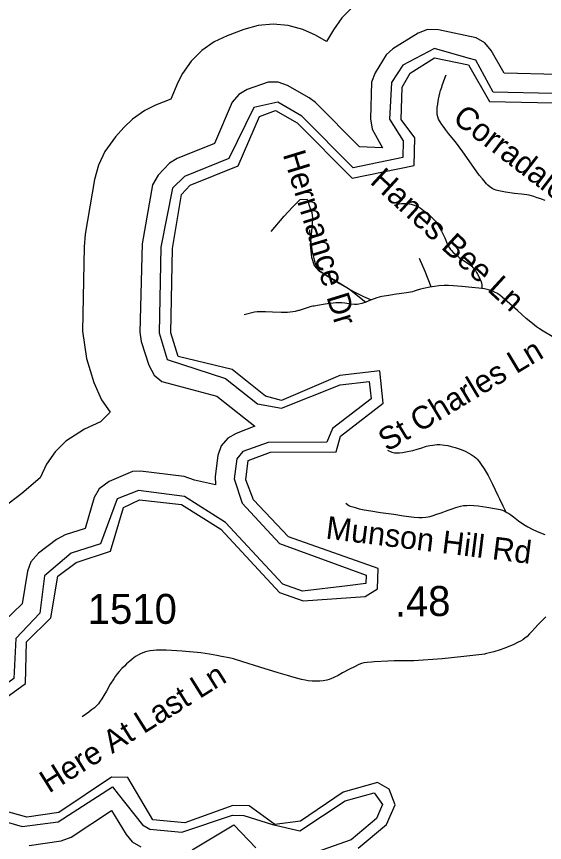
# Model space of a CAD drawing. Extents: x 1383679 to 1536984, y 460658 to 651027.
# Drawn here: x 1385529 to 1387731, y 489995 to 493439 of the extents above; entities that cross this region are included whole.
import ezdxf

# ---------------------------------------------------------------- set-up
doc = ezdxf.new("R2010")
doc.units = 0
for name, color, linetype in [('Exist Hydrographic Bay Label', 7, 'Continuous'), ('Exist Hydrographic Buffer Line', 7, 'Continuous'), ('Exist Road Non-System Type 51', 7, 'Continuous'), ('Exist Road Non-System Type 51 Label', 7, 'Continuous'), ('Exist Road Secondary Mileage Hundredths English Label', 7, 'Continuous'), ('Exist Road Secondary Type 41 Attributed', 7, 'Continuous'), ('Exist Road Secondary Type 51 Label', 7, 'Continuous'), ('Exist Road Secondary Type 51 Number Label', 7, 'Continuous')]:
    doc.layers.add(name, color=color, linetype=linetype)

msp = doc.modelspace()

# ---------------------------------------------------------------- linework, layer by layer
at = {"layer": 'Exist Hydrographic Bay Label'}
for points in [[(1385974.5, 491392), (1386041.5, 491423.5), (1386216.5, 491403.6), (1386380.4, 491301.8), (1386625.4, 491037.5), (1386724.5, 491002.7), (1386983.4, 491020.5), (1387034.4, 491052.3), (1387036.4, 491137.7), (1386663.5, 491269.9), (1386516.4, 491423.8), (1386485.5, 491506.5), (1386495.4, 491588.3), (1386587.4, 491622.6), (1386862.5, 491623.6), (1386880.4, 491688.9), (1387058.4, 491826.4), (1387044.4, 491961.3), (1386877.4, 491941.7), (1386633.4, 491838.3), (1386567.4, 491856), (1386427.5, 491967.1), (1386203.4, 492020.9), (1386172.5, 492120), (1386179.5, 492471.1), (1386217.5, 492696.8), (1386252.5, 492735.5), (1386453.4, 492816.8), (1386541.5, 493021.8), (1386608.4, 493046.7), (1386699.5, 492995.7), (1386928.4, 492764.6), (1387187.4, 492818.5), (1387190.4, 492933.3), (1387133.4, 493010), (1387136.4, 493144.5), (1387170.4, 493202.9), (1387272.4, 493266.5), (1387413.4, 493237.4), (1387501.4, 493084.6), (1387768.4, 493079.3)], [(1385355.5, 490505), (1385566.5, 490658.3), (1385570.5, 490832.2), (1385672.5, 490931.9), (1385701.5, 491105.3), (1385777.5, 491162.9), (1385920.5, 491209.2), (1385974.5, 491392)], [(1386953.4, 489970.8), (1387072.4, 490070.1), (1387107.4, 490151.5), (1387083.4, 490217.6), (1387034.4, 490244.8), (1386891.4, 490205.1), (1386713.4, 490083.8), (1386605.4, 490069.6), (1386498.4, 490147.3), (1386431.4, 490148.6), (1386230.4, 490077.2), (1386097.4, 490089.6), (1385992.5, 490265.7), (1385925.5, 490267.1), (1385705.5, 490120.5), (1385572.5, 490100.2), (1385381.5, 490153.3)]]:
    msp.add_lwpolyline(points, dxfattribs=at)
at = {"layer": 'Exist Hydrographic Buffer Line'}
for p, q in [((1386619.2, 493081.6), (1386518.7, 493059.3)), ((1386533.7, 491824.7), (1386633.6, 491806.3))]:
    msp.add_line(p, q, dxfattribs=at)
for points in [[(1386930.3, 493478.6), (1386885.9, 493434.2), (1386850.7, 493384.1), (1386821.9, 493334.8), (1386775.7, 493360.7), (1386722.7, 493385), (1386662.2, 493401.2), (1386599.6, 493406.7), (1386537.1, 493401.2), (1386476.5, 493385), (1386407.1, 493359.2), (1386352.6, 493333.6), (1386301.3, 493297.6), (1386256.9, 493253.2), (1386220.9, 493201.8), (1386201.9, 493163.8), (1386172.3, 493094.9), (1386108.7, 493069.3), (1386063.6, 493047.3), (1386012.2, 493011.3), (1385976.4, 492976.6), (1385941.4, 492937.9), (1385896.9, 492876.7), (1385870.3, 492819.9), (1385854.1, 492759.2), (1385815.7, 492530.9), (1385810.7, 492478.2), (1385803.7, 492127.1), (1385820.1, 492012.6), (1385851.1, 491913.5), (1385882.8, 491840.9), (1385918.8, 491789.5), (1385879.5, 491749.2), (1385812.5, 491717.8), (1385734.3, 491667.8), (1385689.9, 491623.4), (1385653.9, 491572), (1385627.4, 491515.1), (1385551.2, 491449.8), (1385475.2, 491392.2)], [(1387783.5, 493196.8), (1387562.7, 493203.2), (1387508.6, 493297.2), (1387481.7, 493329.2), (1387445.7, 493350.1), (1387287.9, 493384), (1387242.8, 493384.6), (1387203.6, 493370.3), (1387098.1, 493304.6), (1387069.7, 493280), (1387024, 493204.9), (1387009.4, 493165.2), (1387004.7, 493012.6), (1387011.9, 492968.8), (1387054.8, 492891.1), (1386959, 492895.3), (1386775.9, 493080.1)], [(1387412.6, 493264.9), (1387271.7, 493305.6), (1387140.4, 493236.7), (1387093.1, 493164.6), (1387084.7, 493010.8), (1387141.3, 492920.4), (1387139.4, 492851.1), (1386932.7, 492808.1), (1386719.1, 493023.8), (1386619.2, 493081.6)], [(1389588.2, 491540.1), (1389338.3, 491817.7), (1389047.3, 491821.9), (1389043.8, 491936.8), (1389066.1, 491987), (1389072.5, 492143.6), (1389002.9, 492227.1), (1388866.4, 492265.3), (1388869.5, 492400.2), (1388843.5, 492486.5), (1388767.8, 492563.6), (1388464.1, 492683.2), (1388410.9, 492732.7), (1388318.2, 492943.6), (1388233, 493019), (1387767.6, 493118.4), (1387516, 493124.1), (1387444.3, 493257), (1387412.6, 493264.9)], [(1386775.9, 493080.1), (1386749.4, 493100.3), (1386658.4, 493151.4), (1386620.4, 493164.9), (1386578.8, 493164.9), (1386490.8, 493134.3), (1386455.6, 493113.7), (1386428.7, 493081.8), (1386353.9, 492909.5), (1386198.6, 492846.7), (1386166.5, 492827.4), (1386119.6, 492777.1), (1386095.9, 492737.8), (1386052.3, 492491), (1386043.7, 492122.3), (1386049.1, 492084.2), (1386080.1, 491985.1), (1386102.7, 491943.7), (1386134.7, 491917), (1386364.8, 491856.6), (1386484, 491762.1), (1386522.3, 491731.3)], [(1386619.2, 493081.6), (1386518.7, 493059.3), (1386414.3, 492847.7), (1386228.7, 492772.6), (1386178.9, 492723.5), (1386131.2, 492477.7), (1386123.7, 492120.7), (1386156.5, 492008.9), (1386400.7, 491930.3), (1386533.7, 491824.7)], [(1386633.6, 491806.3), (1386879, 491902.6), (1387000.1, 491916.8), (1387007.6, 491844.4), (1386847.1, 491720.6), (1386823.1, 491663.5), (1386578.5, 491662.6), (1386472.7, 491625.8), (1386447.3, 491595.2), (1386437, 491511.3), (1386470.2, 491409.7), (1386625.8, 491242.2), (1386987, 491109.6), (1386986.1, 491074.8), (1386909.3, 491065.6), (1386721.1, 491043.1), (1386639.2, 491072), (1386400.9, 491329), (1386228.8, 491437.6), (1386037.2, 491463.2), (1385948.7, 491428.2), (1385879.3, 491240.8), (1385756.3, 491200.9)], [(1386522.3, 491731.3), (1386444.8, 491700.8), (1386409.5, 491680.2), (1386382.7, 491648.3), (1386368.4, 491609.1), (1386357.5, 491520.9), (1386358.5, 491485.6)], [(1386358.5, 491485.6), (1386270.9, 491505.5), (1386228.5, 491521.7), (1386046.2, 491542.7), (1386011.8, 491541.6), (1385914.6, 491500.6), (1385873.7, 491469.1), (1385852.9, 491433.1), (1385814.5, 491303.9), (1385731.6, 491277.1), (1385696.2, 491258.6), (1385620.2, 491201), (1385588.7, 491165.3), (1385574.5, 491126.1), (1385551.8, 490990.4), (1385477.8, 490918)], [(1385756.3, 491200.9), (1385645.1, 491107.4), (1385626.3, 490951.4), (1385526.4, 490845), (1385518.1, 490679), (1385323.2, 490537.4), (1385246.9, 490335.3)], [(1385246.9, 490335.3), (1385271.4, 490178.9), (1385350.5, 490120.1), (1385552.9, 490061.7), (1385702.7, 490081), (1385928.4, 490226.9), (1385952.5, 490196.7), (1386054.3, 490069.1), (1386084.9, 490049.8), (1386217.9, 490037.4), (1386429.1, 490108.5), (1386476.3, 490107.5), (1386596.6, 490069.6), (1386709.8, 490044.1), (1386899.6, 490168.3), (1387020.5, 490201.9), (1387055.6, 490152.7), (1387030.6, 490094.6), (1386924.5, 490006), (1386755.2, 489946.3)], [(1385581.8, 489981.6), (1385714.8, 490001.9), (1385756.6, 490016.6), (1385925.5, 490128.8), (1385985.6, 490028.2), (1386011.5, 489997.7), (1386047.6, 489976.9)], [(1386261.8, 489964.1), (1386435.7, 490068.3), (1386526.2, 489972.5)]]:
    msp.add_lwpolyline(points, dxfattribs=at)
at = {"layer": 'Exist Road Non-System Type 51'}
for points in [[(1387732.8, 492672.3), (1387717.8, 492677.3), (1387714.7, 492678.4), (1387700.1, 492683.2), (1387685.5, 492688.1), (1387667.1, 492693.7), (1387656.7, 492695.7), (1387635.2, 492698.5), (1387605.6, 492701.6), (1387567.4, 492706.7), (1387553.9, 492708.9), (1387540, 492711.7), (1387529.6, 492714.5), (1387521.2, 492717.6), (1387512.3, 492722.1), (1387502.1, 492729.2), (1387494.6, 492736), (1387489.4, 492741.4), (1387471.6, 492762.3), (1387458.5, 492778), (1387426, 492824), (1387389.8, 492874.7), (1387359.5, 492916.3), (1387330.5, 492951.8), (1387318.3, 492968.1), (1387311.6, 492976.5), (1387302, 492989.4), (1387294.9, 493000.5), (1387293.1, 493004.2), (1387289.1, 493011.8), (1387285.6, 493020.7), (1387283.6, 493030.1), (1387282.7, 493041.3), (1387282.7, 493054.6), (1387283.7, 493063.1), (1387284.4, 493066), (1387289.1, 493094.8), (1387294.6, 493119.2), (1387297.4, 493130.2), (1387302, 493143.9), (1387304.3, 493151.8), (1387309.5, 493167.2), (1387314.4, 493181.5), (1387320, 493196.6)], [(1386590.2, 492542.8), (1386645.2, 492606.8), (1386680.1, 492643.5), (1386711.2, 492676.5), (1386741, 492677.6), (1386752.1, 492643.2), (1386760.4, 492622.3), (1386763.5, 492598.8), (1386762.4, 492573.2), (1386753.2, 492487.4), (1386759.4, 492435.2), (1386770.6, 492401.5), (1386791, 492377), (1386852.4, 492342.2), (1386916.8, 492302.3), (1386985.8, 492248.3)], [(1387104, 492651.9), (1387116.6, 492655.9), (1387124.7, 492657.8), (1387134.5, 492659), (1387144.6, 492659.4), (1387154.4, 492658.9), (1387165.9, 492657.9), (1387174.2, 492656.5), (1387183.3, 492654.3), (1387194.3, 492650.4), (1387202.3, 492646.6), (1387212, 492640.9), (1387226.3, 492630.6), (1387235.9, 492622.9), (1387242.3, 492617.3), (1387253.3, 492608), (1387260.4, 492601.7), (1387268.8, 492593.3), (1387275.9, 492585.5), (1387280.3, 492579.6), (1387291.9, 492561.3), (1387301.4, 492544.2), (1387314.3, 492516.7), (1387325.4, 492490.7), (1387330.5, 492480.6), (1387333.6, 492475.3), (1387338.5, 492468.2), (1387342.3, 492463.2), (1387349.2, 492455.8), (1387360.3, 492446.1), (1387374.7, 492434.9), (1387401.2, 492416.6), (1387420.2, 492403.1), (1387426.9, 492397.8), (1387432.4, 492392.6), (1387438.4, 492385.6), (1387443.2, 492379.4), (1387447.4, 492372.1), (1387450.9, 492365.2), (1387456.2, 492355.6), (1387461.5, 492344.8), (1387463.7, 492339.6), (1387466.1, 492333.2), (1387467.6, 492328.3), (1387469, 492318.3), (1387469, 492305.4)], [(1386750.7, 492549.6), (1386751.3, 492544.3), (1386757.7, 492487.5), (1386760.7, 492467.2), (1386761.9, 492459.9), (1386763.8, 492451.8), (1386765.3, 492444), (1386767, 492435.7), (1386769.9, 492424.6), (1386772.7, 492415), (1386774.9, 492408.1), (1386777.2, 492401.7), (1386779.7, 492396), (1386783.2, 492390), (1386786, 492386.2), (1386788.9, 492383), (1386794.3, 492378.2), (1386801.8, 492372.7), (1386807.6, 492368.8), (1386812.6, 492365.1), (1386821.2, 492359.8), (1386876.1, 492325.2), (1386934.4, 492292), (1386975.9, 492271.4), (1386985.2, 492267.4), (1387008.1, 492257.6)], [(1387207.8, 492431), (1387231.5, 492377.8), (1387256, 492312.9)], [(1387469, 492305.4), (1387456.8, 492306.4), (1387428.2, 492309.2), (1387386, 492313.8), (1387349.5, 492316.7), (1387330.2, 492317.5), (1387311.7, 492317.4), (1387290.1, 492315.9), (1387271.8, 492314), (1387251.8, 492310.9), (1387225.7, 492305.4), (1387213, 492301.8), (1387199.2, 492297.5), (1387187.7, 492293.7), (1387179.6, 492291.7), (1387154.7, 492286.8), (1387134.1, 492283.6), (1387104, 492279.3), (1387081.3, 492276.1), (1387052.7, 492271.6), (1387041.7, 492268.8), (1387031.3, 492265.8), (1387019.8, 492262.4), (1387008.1, 492257.6)], [(1387845.4, 492055.2), (1387762.4, 492104.5), (1387724.7, 492127.1), (1387710, 492136.9), (1387697.9, 492145), (1387680, 492159.2), (1387654.6, 492179.7), (1387618.7, 492213.5), (1387574.4, 492250.9), (1387554.7, 492268.2), (1387554, 492268.8), (1387544, 492277.1), (1387536.6, 492282.1), (1387532.1, 492284.9), (1387524.4, 492288.7), (1387517.2, 492291.8), (1387509.2, 492295), (1387501.6, 492297.7), (1387496.7, 492299.5), (1387486.6, 492301.9), (1387480.1, 492303.6), (1387469, 492305.4)], [(1387008.1, 492257.6), (1386994.9, 492252.2), (1386986.1, 492248.5), (1386981.8, 492246.7), (1386969.5, 492242.3), (1386956.1, 492239.3), (1386949, 492238.4), (1386938.7, 492238.4), (1386923.2, 492239.9), (1386898.2, 492243.4), (1386885.8, 492244.7), (1386869.7, 492245.7), (1386860.7, 492245.7), (1386848.7, 492244.1), (1386835.7, 492242.1), (1386816.6, 492239.5), (1386784.6, 492234.4), (1386769.7, 492232), (1386764, 492230.9), (1386757.9, 492229.3), (1386707.6, 492213.8), (1386704.7, 492213.1), (1386690.6, 492209.5), (1386680.9, 492207.3), (1386659.4, 492204.9), (1386632.1, 492204.5), (1386596.9, 492206.1), (1386566.5, 492207.2), (1386539.9, 492207.9), (1386532.9, 492207.2), (1386521.5, 492206.4), (1386478.8, 492195.5)], [(1387075.4, 491630.6), (1387093.5, 491622.8), (1387104.9, 491620.1), (1387114, 491619.5), (1387126, 491620.1), (1387139.1, 491621.6), (1387165.7, 491626.3), (1387181.1, 491629.9), (1387199.8, 491635.1), (1387214.8, 491639.6), (1387238.4, 491646.9), (1387252.1, 491650), (1387264.7, 491652.1), (1387281.7, 491653.8), (1387294.6, 491653.8), (1387314.7, 491652.1), (1387327.2, 491650), (1387341.8, 491646.6), (1387357.5, 491642.1), (1387370.7, 491637.9), (1387382.6, 491633.7), (1387399.2, 491626.8), (1387415.1, 491618.8), (1387424.6, 491612.9), (1387437.1, 491604.2), (1387443.6, 491598.6), (1387449.2, 491593.1), (1387457.8, 491583.6), (1387466.5, 491571.5), (1387478.9, 491552.8), (1387495.2, 491524.7), (1387513.8, 491488.7), (1387536.4, 491441.1), (1387542.8, 491428.3), (1387557.3, 491398.9), (1387569.4, 491373.8)], [(1386901.6, 491409.6), (1386914.9, 491400.6), (1386920.5, 491397.8), (1386931.2, 491394), (1386940.5, 491391.5), (1386958.4, 491386.7), (1386978.9, 491382.6), (1387006.5, 491377.3), (1387047.4, 491371), (1387102.4, 491363.4), (1387143.3, 491357.4), (1387187, 491352), (1387206.7, 491350.3), (1387220.3, 491349.9), (1387235.6, 491350.8), (1387246, 491353), (1387253.3, 491354.8), (1387266.8, 491359), (1387277.3, 491362.1), (1387299.1, 491369.7), (1387329.1, 491380.7), (1387345.1, 491386.6), (1387361, 491391.8), (1387380.1, 491396.9), (1387393.4, 491399.4), (1387407.1, 491400.3), (1387418.7, 491400.8), (1387436.6, 491400.5), (1387454.3, 491398.8), (1387489.9, 491393.6), (1387531.1, 491386), (1387538.9, 491384.5), (1387545.4, 491383.2), (1387554.9, 491380.7), (1387561.8, 491378), (1387569.4, 491373.8)], [(1387569.4, 491373.8), (1387573.9, 491371.4), (1387581.3, 491366.8), (1387590.1, 491360.8), (1387601.7, 491352.3), (1387622.3, 491336.8), (1387644.5, 491321), (1387661.5, 491311), (1387679.5, 491300.8), (1387700.4, 491291.2), (1387732, 491278.7)]]:
    msp.add_lwpolyline(points, dxfattribs=at)
at = {"layer": 'Exist Road Secondary Type 41 Attributed'}
for points in [[(1387735.5, 490935.8), (1387725.1, 490925.4), (1387704.6, 490903.8), (1387690.3, 490889.2), (1387677.7, 490875.3), (1387668.1, 490864.9), (1387657.7, 490854.2), (1387649, 490846.2), (1387640.7, 490840.3), (1387631, 490834.7), (1387621.2, 490829.5), (1387602.8, 490820.8), (1387578.8, 490810.4), (1387560.5, 490803.5), (1387545.1, 490798.3), (1387519.3, 490790.4), (1387501.7, 490785.5), (1387488.7, 490782.5), (1387481.1, 490780.6), (1387469.6, 490778.9), (1387393.8, 490770.1), (1387303.5, 490760.1), (1387185.4, 490752.5), (1387142.6, 490751.9), (1387103.1, 490751.7), (1387077.4, 490751.3), (1387020.2, 490748.5), (1387008.9, 490747.4), (1386991.2, 490746), (1386977.5, 490744), (1386967.5, 490740.8), (1386956.1, 490736.6), (1386937.7, 490727.9), (1386916.8, 490717.3), (1386888.8, 490702.4), (1386869.9, 490691.6), (1386851.6, 490682.2), (1386839.4, 490676.9), (1386832.5, 490674.6), (1386822.8, 490671.4), (1386808.2, 490668.6), (1386794.3, 490667.5), (1386783.2, 490666.9), (1386772.7, 490666.9), (1386761.6, 490667.5), (1386744.9, 490669.2), (1386732.8, 490671.4), (1386717, 490674.9), (1386686.2, 490682.3), (1386658.8, 490690.6), (1386620, 490702.7), (1386543.5, 490725.7), (1386472, 490748.1), (1386433.5, 490760.1), (1386415.9, 490764.4), (1386383.7, 490770.7), (1386364.1, 490774.6), (1386333.8, 490780.2), (1386297.4, 490785.4), (1386220.1, 490793.2), (1386175, 490795.6), (1386152.2, 490796.6), (1386132.7, 490796.6), (1386113, 490796.2), (1386099.8, 490795.6), (1386086.3, 490793.9), (1386072.3, 490791.5), (1386066.7, 490790), (1386055.7, 490786.2), (1386045.6, 490781.7), (1386037.7, 490777.5), (1386028.1, 490771.6), (1386019.3, 490765.7), (1386009.5, 490758.3), (1386000.9, 490751.2), (1385987.9, 490739.7), (1385978.5, 490730.6), (1385968.2, 490720.3)], [(1385968.2, 490720.3), (1385956.7, 490707.8), (1385948.8, 490697.7), (1385940.5, 490686.9), (1385934.1, 490677.6), (1385919.9, 490655), (1385903.9, 490626.3), (1385892.9, 490607.1), (1385884.8, 490593.6), (1385875.4, 490579.4), (1385870.5, 490573.3), (1385865.1, 490567.4), (1385853.8, 490556.8), (1385842, 490547.7), (1385830, 490538.9), (1385802.8, 490518.6)]]:
    msp.add_lwpolyline(points, dxfattribs=at)

# ---------------------------------------------------------------- texts
at = {"layer": 'Exist Road Non-System Type 51 Label'}
for s, rotation, p in [('Corradale Rd', 322.5497, (1387342.6, 493004.2)), ('Hermance Dr', 287.0356, (1386638.5, 492864.5)), ('Hanes Bee Ln', 317.49, (1386998.8, 492746.4)), ('St Charles Ln', 31.1011, (1387074.4, 491622.5)), ('Munson Hill Rd', 352.9513, (1386815.5, 491262.2))]:
    msp.add_text(s, height=95, rotation=rotation, dxfattribs=at).set_placement(p)
at = {"layer": 'Exist Road Secondary Mileage Hundredths English Label'}
msp.add_text('.48', height=125, rotation=0.7663, dxfattribs=at).set_placement((1387106.8, 490936.8))
at = {"layer": 'Exist Road Secondary Type 51 Label'}
msp.add_text('Here At Last Ln', height=95, rotation=32.1119, dxfattribs=at).set_placement((1385664.1, 490198.3))
at = {"layer": 'Exist Road Secondary Type 51 Number Label'}
msp.add_text('1510', height=125, dxfattribs=at).set_placement((1385825.7, 490906.5))

doc.saveas('drawing.dxf')
